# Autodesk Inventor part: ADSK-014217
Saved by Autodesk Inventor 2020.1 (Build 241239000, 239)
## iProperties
_SkeletonDoc: Frame Skeleton File
_Version: 15.0.0
Part Number: ADSK-014217
Material: Allgemein
Description: Framegenerator-Skeleton-Referenz
Document SubType Name: Modellieren
Designer: lutzd
Density: 1 g/cm^3
Appearance: Vorgabe
DocNumber: ADSK-014217
Folder: .
Dimensions: 0x0x0 mm
Mass: 0 kg
Title: Gestellrahmenbauteil(e)
Author: lutzd
Revision Number: -
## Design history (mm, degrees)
sketch "Referenzrahmen"
node "Volumenkörper"
node "Flächenkörper"
